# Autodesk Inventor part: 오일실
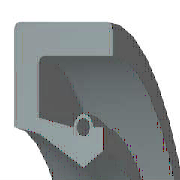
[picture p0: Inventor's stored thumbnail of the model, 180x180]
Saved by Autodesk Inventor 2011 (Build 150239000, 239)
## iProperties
IsCustomPart: 0
Created: 2009-02
Part Number: 오일실
Material: 고무
Description: 오일-실
Document SubType Name: Modeling
Standard: KS B 2804
Designer: 한국산업디자인학원 [http://gmhk.co.kr]
Standards Organization: KS
Language: ko-KR
Size Designation: S - 17 30 8
Categories: <MemberInstance><Categories><Category DisplayName="샤프트 부품" InternalName="7f7aeb1f-a693-4053-b835-cee3144e0d98" Mnemonic="SHFT"><Category DisplayName="실링" Intern
Density: 0.93 g/cm^3
Author: pww
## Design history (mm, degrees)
revolve "본체" stored, may be unused: angle "d17" = 90 deg
revolve "스프링1" stored, may be unused: angle "d18" = 90 deg
body "Solid1"
sketch "스케치1"
  geometry: L1 (0, 15)-(8, 15); L2 (8, 15)-(8, 13.75); L3 (8, 13.75)-(1.75, 13.75); L4 (0, 15)-(0, 10.6); L5 (0, 10.6)-(1.75, 10.25); L6 (1.75, 10.25)-(4.9, 8.5); L7 (4.9, 8.5)-(0, 8.5); L8 (6.3, 9.375)-(6.3, 10.6); L9 (0, 0)-(9.586, 0) reference; L10 (4.9, 8.5)-(6.3, 9.375); L11 (0, 18)-(0, -3) reference; L12 (-1.917, 0)-(11.503, 0) reference; L13 (4.2, 10.6)-(1.75, 11.09); L14 (1.75, 11.09)-(1.75, 13.75); L15 (6.3, 10.6)-(5.6, 10.6); C1 r 0.455 at (4.9, 10.6); A1 r 0.7 centre (4.9, 10.6) between (5.6, 10.6) and (4.2, 10.6)
  constraints: 26 end point, 5 horizontal alignment, 4 perpendicular, 2 centre point, 2 collinear, 2 horizontal, 2 parallel, 2 point on circle, 2 point on line, 2 vertical alignment, 1 coincident
  dimensions: "d0" = 30 diameter of L1 L9 (= SD2); "d1" = 18.75 diameter of L8.start L9 (= ABDM); "d2" = 1.25 distance of L1.end L2.end (computed from SD); "d3" = 0.91 diameter of C1 (= SPDI); "d4" = 1.4 diameter of A1 (= SPDA); "d5" = 17 diameter of L6.end L9 (= NND); "d6" = 20.5 diameter of L5.end L9 (= TKDM); "d7" = 21.2 diameter of L4.end L9 (= HLDM); "d8" = 4.9 distance from line of C1.centre L4 (= SPDST); "d9" = 6.3 distance between parallel lines of L8 L4 (= SDI); "d10" = 8 distance between parallel lines of L2 L4 (= SWDT); "d12" = 1.75 distance between parallel lines of L14 L4 (= SD)
fillet "모깎기1" dims "d11" = 0.3 (= RR)
other parameters: "SD2" = 30 [user parameter; used in 1 equation term], "SWDT" = 8 [user parameter; used in 1 equation term], "RR" = 0.3 [user parameter; used in 1 equation term], "SD" = 1.75 [user parameter; used in 2 equation terms], "NND" = 17 [user parameter; used in 1 equation term], "SPDA" = 1.4 [user parameter; used in 1 equation term], "SPDI" = 0.91 [user parameter; used in 1 equation term], "TKDM" = 20.5 [user parameter; used in 1 equation term], "HLDM" = 21.2 [user parameter; used in 1 equation term], "ABDM" = 18.75 [user parameter; used in 1 equation term], "SDI" = 6.3 [user parameter; used in 1 equation term], "SPDST" = 4.9 [user parameter; used in 1 equation term], "d13" = 0, "d14" = 0, "d15" = 0, "LAB" = 0.35 [user parameter]
